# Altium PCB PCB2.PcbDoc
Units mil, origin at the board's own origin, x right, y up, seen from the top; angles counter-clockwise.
Board outline 1968.5 x 1968.5 mil, 2 copper layers (Top Layer, Bottom Layer); 14 components, 16 nets, 44 pads, 6 vias.
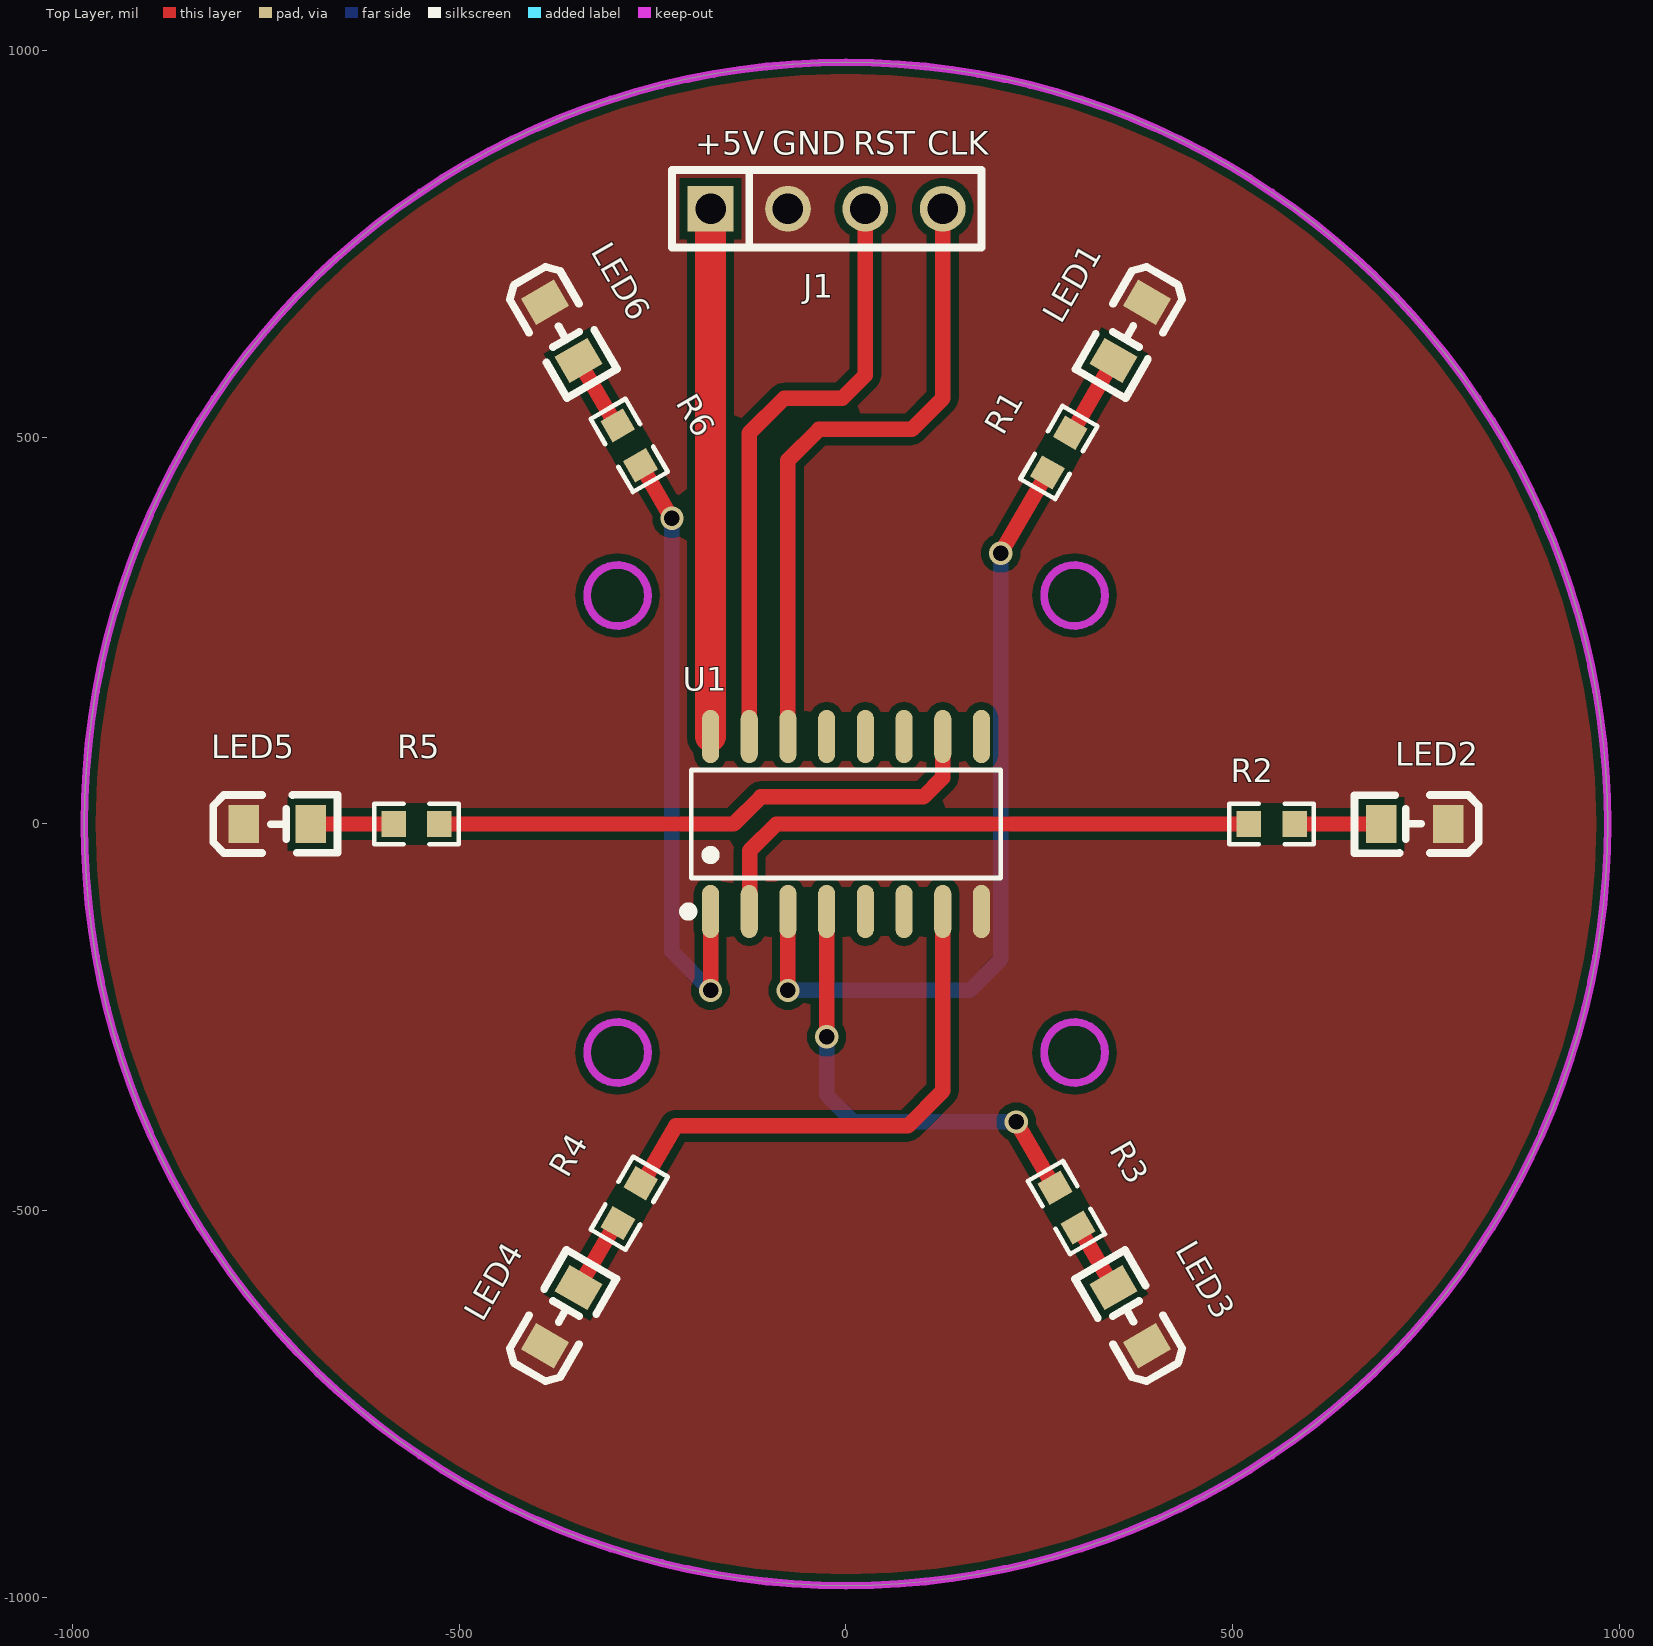
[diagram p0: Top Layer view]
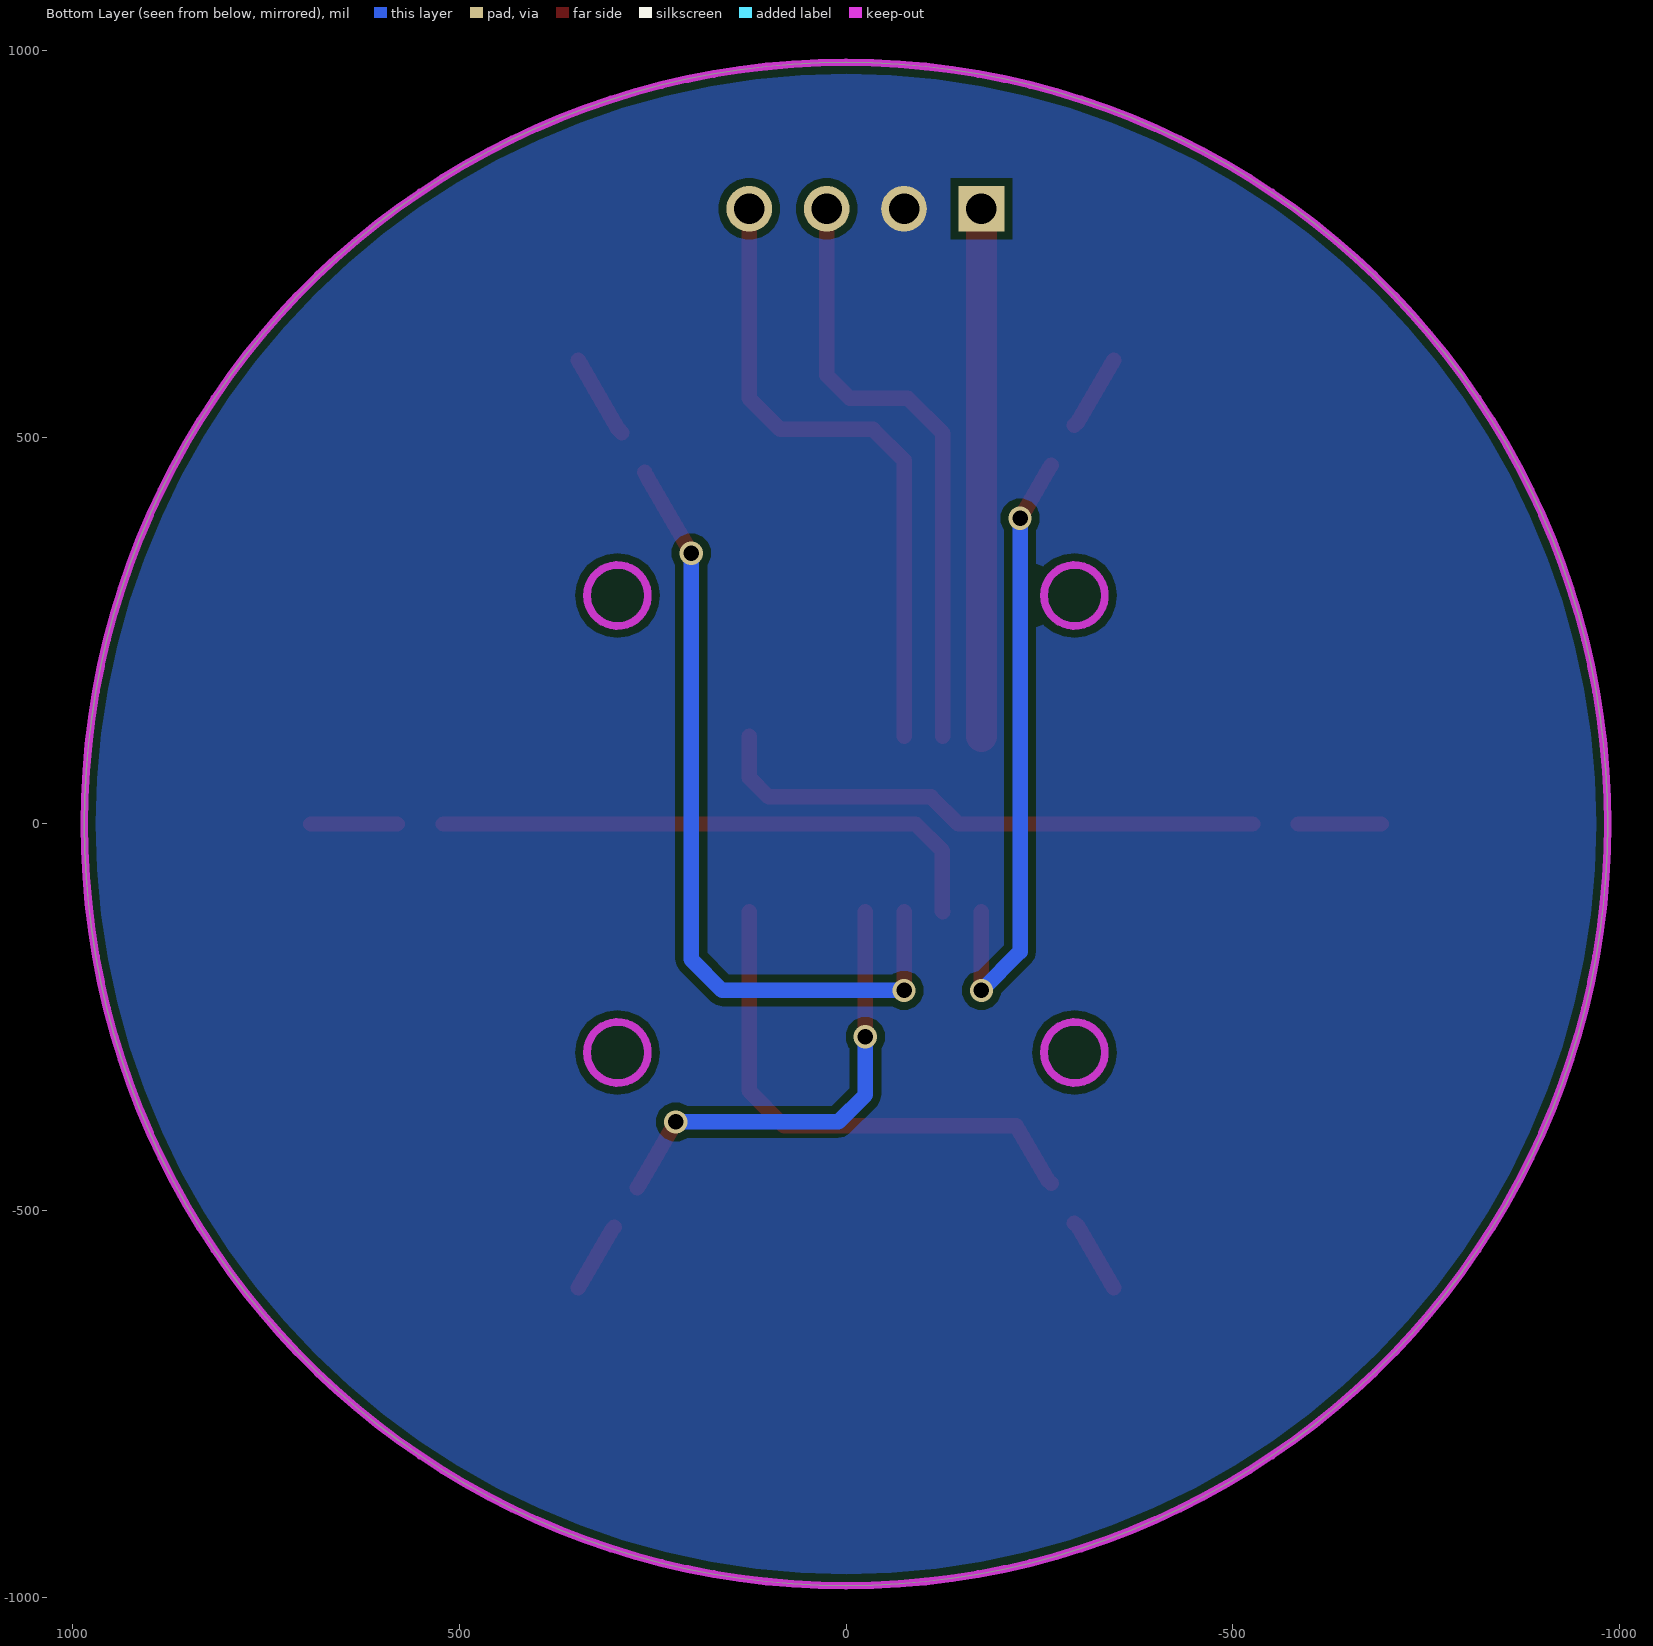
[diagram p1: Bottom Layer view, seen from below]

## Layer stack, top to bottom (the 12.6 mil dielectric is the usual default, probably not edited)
Top Solder: solder mask 0.4, Solder Resist, Dk 3.5
Top Layer: signal copper 1.4
Dielectric 1: dielectric 12.6, FR-4, Dk 4.8
Bottom Layer: signal copper 1.4
Bottom Solder: solder mask 0.4, Solder Resist, Dk 3.5

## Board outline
-984.25,0 ccw(c0,0) 0,-984.25 ccw(c0,0) 984.25,0 ccw(c0,0) 0,984.25 ccw(c0,0)

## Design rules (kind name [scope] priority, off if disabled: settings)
Clearance [All] p1: gap=10 ignorepadtopadclearanceinfootprint=FALSE except(0: Arc-Hole Track-Hole SMDPad-Hole THPad-Hole Via-Hole Fill-Hole Poly-Hole Region-Hole Text-Hole)
PlaneConnect [All] p1: planeconnectstyle=Direct reliefexpansion=20 reliefentries=4 reliefconductorwidth=10 reliefairgap=10
PolygonConnect [All] p1: connectstyle=Direct reliefconductorwidth=10 reliefentries=4 polygonreliefangle="90 Angle" airgapwidth=10
RoutingVias [All] p1: holewidth=28 width=50 viastyle="Through Hole" minholewidth=1 minwidth=1 maxholewidth=28 maxwidth=50
SilkToSolderMaskClearance [IsPad] p1: minsilkscreentomaskgap=5 clearancetoexposedcopper=TRUE
SolderMaskExpansion [All] p1: expansion=4 istentingtop=FALSE
Width [All] p1: maxlimit=100 minlimit=1 preferedwidth=10
28 further rules are at their usual default settings.

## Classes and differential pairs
component class Sheet1: J1 LED1 LED2 LED4 LED5 R1 R2 R3 R4 R5 U1

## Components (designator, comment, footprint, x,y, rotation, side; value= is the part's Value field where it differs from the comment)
J1 "CON4" SIP4 -175,795 r0 top
LED1 "XL-2012SURC" LED0805-RD_RED 367.52,636.56 r240 top
LED2 "XL-2012SURC" LED0805-RD_RED 735.04,0 r180 top
LED3 "XL-2012SURC" LED0805-RD_RED 367.52,-636.56 r120 top
LED4 "XL-2012SURC" LED0805-RD_RED -367.52,-636.56 r60 top
LED5 "XL-2012SURC" LED0805-RD_RED -735.04,0 r0 top
LED6 "XL-2012SURC" LED0805-RD_RED -367.52,636.56 r300 top
R1 "220Ω" R0603 275,480 r240 top
R2 "220Ω" R0603 550,0 r180 top
R3 "220Ω" R0603 284.83,-495.69 r120 top
R4 "220Ω" R0603 -280,-490 r60 top
R5 "220Ω" R0603 -555,0 r180 top
R6 "220Ω" R0603 -280.17,489.31 r300 top
U1 "HEF4017BT,653" SOP-16_L10.0-W3.9-P1.27-LS6.0-BL 0,0 r0 top

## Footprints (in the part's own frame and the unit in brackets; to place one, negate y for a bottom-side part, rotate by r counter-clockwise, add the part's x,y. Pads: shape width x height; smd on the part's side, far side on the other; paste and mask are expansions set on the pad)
LED0805-RD_RED [mm]
  rect 1x1.25 smd: 1(-1.1,0) 2(1.1,0)
  silkscreen extent -2.1,-0.95 1.98,0.96
R0603 [mil]
  rect 31.75x34.02 smd: 1(-29.66,0) 2(29.66,0)
  silkscreen extent -55,-26 55,26
SIP4 [mm]
  rect 1.5x1.5 hole 1: 1(0,0)
  round 1.5 hole 1: 2(2.54,0) 3(5.08,0) 4(7.62,0)
  silkscreen extent -1.27,-1.27 8.89,1.27
SOP-16_L10.0-W3.9-P1.27-LS6.0-BL [mm]
  oval 0.56x1.745 smd: 1(-4.445,-2.872) 2(-3.175,-2.872) 3(-1.905,-2.872) 4(-0.635,-2.872) 5(0.635,-2.872) 6(1.905,-2.872) 7(3.175,-2.872) 8(4.445,-2.872) 9(4.445,2.872) 10(3.175,2.872) 11(1.905,2.872) 12(0.635,2.872) 13(-0.635,2.872) 14(-1.905,2.872) 15(-3.175,2.872) 16(-4.445,2.872)
  silkscreen extent -5.33,-3.02 5.08,1.77

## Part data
J1: "Connector"
LED1 LED2 LED3 LED4 LED5 LED6: Color Temperature=-, Emitted Color=红色, Forward Current=25mA, JLCPCB Part Class=扩展库, Lens Color=无色透明透镜, Manufacturer=XINGLIGHT(成兴光), Operating Temperature=-30℃~+85℃, Power Dissipation=55mW
R1 R2 R3 R4 R5 R6: library part 0603WAF2200T5E, JLCPCB Part Class=基础库, LCSC Part Name="220Ω ±1% 100mW 厚膜电阻", Manufacturer=UNI-ROYAL(厚声), Operating Temperature Range=-55℃~+155℃, Overload Voltage (Max)=75V, Power(Watts)=100mW, Temperature Coefficient=±100ppm/℃, Tolerance=±1%
U1: JLCPCB Part Class=扩展库, LCSC Part Name="30MHz 10位十进制计数器", Manufacturer=Nexperia(安世), Operating Temperature=-40℃~+85℃, Voltage - Supply=4.5V~15.5V

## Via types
v1: diameter 30, hole 20, Top Layer to Bottom Layer, 6 vias

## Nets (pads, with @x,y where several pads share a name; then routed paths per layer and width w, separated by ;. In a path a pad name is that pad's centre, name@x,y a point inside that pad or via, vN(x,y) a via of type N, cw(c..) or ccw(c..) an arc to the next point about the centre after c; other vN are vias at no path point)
+5V: J1.1 U1.16 | length 681.9
  Top Layer w40: U1.16 J1.1
CLK: J1.4 U1.14 | length 835
  Top Layer w20: U1.14 -75,470 -35,510 85,510 125,550 J1.4
GND: J1.2 LED1.1 LED2.1 LED3.1 LED4.1 LED5.1 LED6.1 U1.8
NetLED1_2: LED1.2 R1.1 | length 109.1
  Top Layer w20: R1.1 294.23,509.93 340.88,590.75 LED1.2
NetLED2_2: LED2.2 R2.1 | length 112.1
  Top Layer w20: R2.1 585.54,0 682.05,0 LED2.2
NetLED3_2: LED3.2 R3.1 | length 90.5
  Top Layer w20: R3.1 303.5,-525.94 340.91,-590.73 LED3.2
NetLED4_2: LED4.2 R4.1 | length 98.1
  Top Layer w20: LED4.2 -340.81,-590.79 -299.73,-519.64 R4.1
NetLED5_2: LED5.2 R5.2 | length 107.1
  Top Layer w20: LED5.2 -682.05,0 -590.54,0 R5.2
NetLED6_2: LED6.2 R6.1 | length 98.5
  Top Layer w20: LED6.2 -340.85,590.77 -299.51,519.18 R6.1
NetR1_2: R1.2 U1.3 | length 1038.9
  Top Layer w20: v1(-75,-215) U1.3 ; v1(200,350) 257.27,449.2 R1.2
  Bottom Layer w20: v1(-75,-215) 160,-215 200,-175 v1(200,350)
NetR2_2: R2.2 U1.2 | length 737.9
  Top Layer w20: U1.2 -124.61,-112.7 -124.61,-34.61 -90,0 R2.2
NetR3_2: R3.2 U1.4 | length 595.1
  Top Layer w20: v1(-25,-275) U1.4 ; v1(220,-385) 266.37,-465.31 R3.2
  Bottom Layer w20: v1(-25,-275) -25,-350 10,-385 v1(220,-385)
NetR4_2: R4.2 U1.7 | length 682.8
  Top Layer w20: R4.2 -260.53,-460.21 -220,-390 80,-390 125,-345 U1.7
NetR5_1: R5.1 U1.10 | length 728.3
  Top Layer w20: R5.1 -145,0 -110,35 100,35 125,60 U1.10
NetR6_2: R6.2 U1.1 | length 812.3
  Top Layer w20: R6.2 -261.86,458.85 v1(-225,395) ; v1(-175,-215) U1.1
  Bottom Layer w20: v1(-225,395) -225,-165 v1(-175,-215)
RST: J1.3 U1.15 | length 788
  Top Layer w20: U1.15 -125,505 -80,550 -5,550 25,580 J1.3
pads on no net: U1.5 U1.6 U1.9 U1.11 U1.12 U1.13

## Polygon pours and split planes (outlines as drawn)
GND on Bottom Layer "G" (solid, remove dead copper, pour order 0): -1047.44,1035 1015,1035 1015,-1020 -1022.62,-1020
GND on Top Layer "G" (solid, remove dead copper, pour order 1): -1047.44,1035 1015,1035 1015,-1020 -1022.62,-1020

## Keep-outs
Keep-Out Layer:
  circle w10: c-295.28,-295.28 r39.37
  circle w10: c295.28,-295.28 r39.37
  circle w10: c-295.28,295.28 r39.37
  circle w10: c295.28,295.28 r39.37
  circle w10: c0,0 r984.25

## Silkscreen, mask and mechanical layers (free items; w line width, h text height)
Top Overlay:
  text "+5V" at -195,865.01 h30
  text "GND" at -95.24,865.01 h30
  text "RST" at 9.52,865.01 h30
  text "CLK" at 105,865.01 h30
